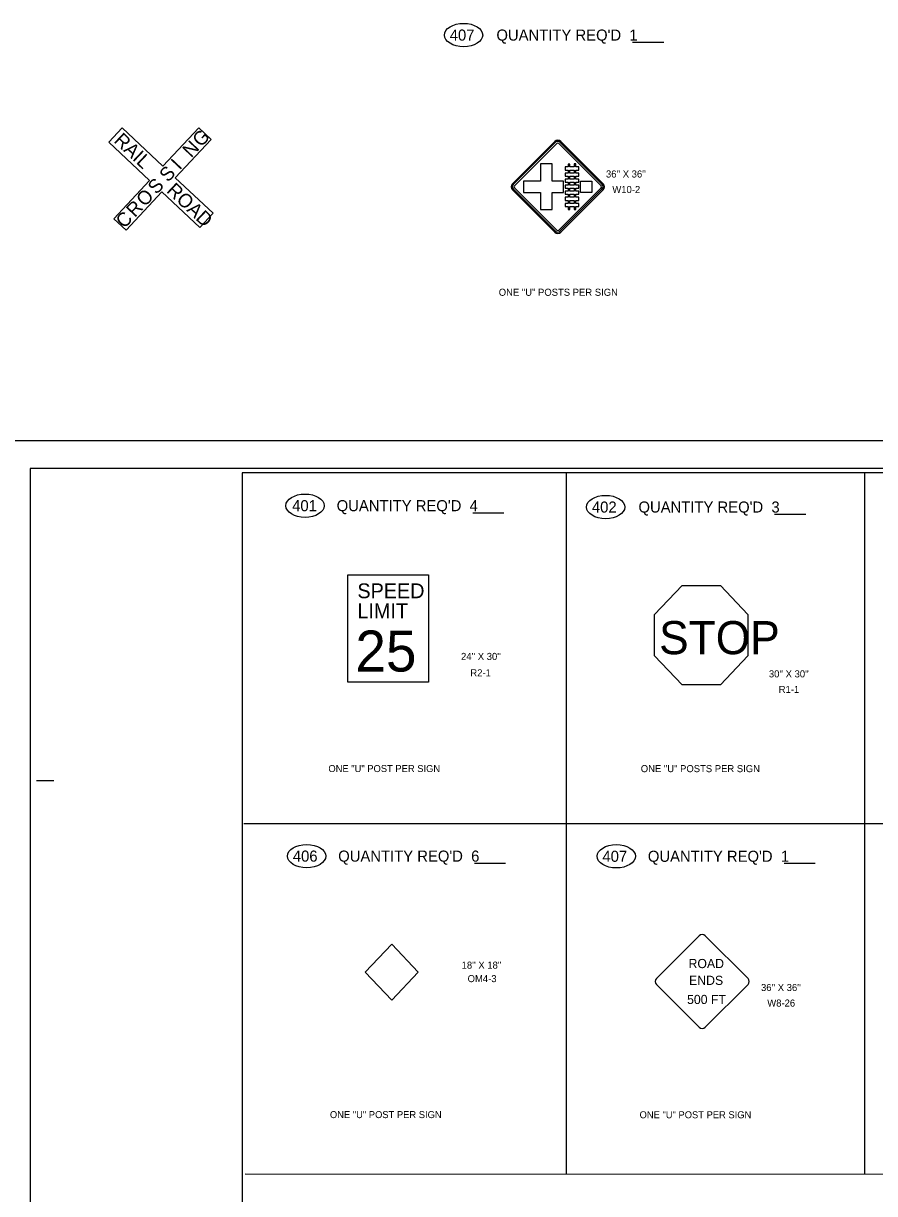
# Model space of a CAD drawing. Extents: x 2088420 to 2091362, y 751309 to 752707.
# Drawn here: x 2089077 to 2089693, y 751860 to 752707 of the extents above; entities that cross this region are included whole.
import ezdxf

# ---------------------------------------------------------------- set-up
doc = ezdxf.new("R2010")
doc.units = 0
for name, color, linetype in [('Default', 7, 'Continuous'), ('Prop Sign E', 7, 'Continuous'), ('Prop Text', 7, 'Continuous'), ('Sheet Block Title CELL', 7, 'Continuous'), ('Sheet Plot Border Inside CELL', 7, 'Continuous'), ('Sheet Plot Border Outside CELL', 7, 'Continuous')]:
    doc.layers.add(name, color=color, linetype=linetype)

msp = doc.modelspace()

# ---------------------------------------------------------------- linework, layer by layer
at = {"layer": 'Default'}
for p, q in [((2089469.52, 752381.51), (2089469.52, 752127.69)), ((2089685.4, 752381.62), (2089685.4, 752127.69)), ((2089236.2, 752127.69), (2090367.92, 752127.69)), ((2089469.52, 752127.69), (2089469.52, 751873.86)), ((2089685.4, 752127.8), (2089685.4, 751873.86)), ((2089237.3, 751873.98), (2090367.92, 751873.63))]:
    msp.add_line(p, q, dxfattribs=at)
for points in [[(2089311.54, 752229.8), (2089311.54, 752307.57), (2089369.91, 752307.57), (2089369.91, 752229.8)], [(2089533.57, 752278.84), (2089553.36, 752299.91), (2089581.32, 752299.91), (2089601.11, 752278.84), (2089601.11, 752249.04), (2089581.32, 752227.96), (2089553.36, 752227.96), (2089533.57, 752249.04)], [(2089343.25, 751999.57), (2089324.14, 752019.93), (2089343.25, 752040.29), (2089362.36, 752019.93)]]:
    msp.add_lwpolyline(points, close=True, dxfattribs=at)
at = {"layer": 'Prop Sign E'}
for p, q in [((2089138.42, 752620.78), (2089148.12, 752631.16)), ((2089148.12, 752631.16), (2089177.71, 752603.48)), ((2089177.71, 752603.48), (2089203.6, 752631.16)), ((2089203.6, 752631.16), (2089212.51, 752622.82)), ((2089168.01, 752593.11), (2089138.42, 752620.78)), ((2089212.51, 752622.82), (2089186.62, 752595.14)), ((2089461.25, 752621.37), (2089430.62, 752590.74)), ((2089461.86, 752620.76), (2089431.23, 752590.13)), ((2089432.08, 752589.28), (2089462.71, 752619.91)), ((2089464.17, 752619.91), (2089494.79, 752589.28)), ((2089495.64, 752590.13), (2089465.02, 752620.76)), ((2089496.25, 752590.74), (2089465.62, 752621.37)), ((2089142.12, 752565.43), (2089168.01, 752593.11)), ((2089186.62, 752595.14), (2089214.07, 752569.47)), ((2089176.92, 752584.77), (2089151.03, 752557.09)), ((2089204.36, 752559.1), (2089176.92, 752584.77)), ((2089430.62, 752586.36), (2089461.25, 752555.74)), ((2089431.23, 752586.97), (2089461.86, 752556.35)), ((2089462.71, 752557.2), (2089432.08, 752587.82)), ((2089494.79, 752587.82), (2089464.17, 752557.2)), ((2089465.02, 752556.35), (2089495.64, 752586.97)), ((2089465.62, 752555.74), (2089496.25, 752586.36)), ((2089214.07, 752569.47), (2089204.36, 752559.1)), ((2089151.03, 752557.09), (2089142.12, 752565.43)), ((2089565.76, 752046.38), (2089534.8, 752015.42)), ((2089601.13, 752015.42), (2089570.17, 752046.38)), ((2089534.8, 752011.01), (2089565.76, 751980.05)), ((2089570.17, 751980.05), (2089601.13, 752011.01))]:
    msp.add_line(p, q, dxfattribs=at)
for points in [[(2089467.56, 752584.43), (2089467.56, 752592.68), (2089459.31, 752592.68), (2089459.31, 752605.05), (2089451.06, 752605.05), (2089451.06, 752592.68), (2089438.69, 752592.68), (2089438.69, 752584.43), (2089451.06, 752584.43), (2089451.06, 752572.05), (2089459.31, 752572.05), (2089459.31, 752584.43)], [(2089478.6, 752600.68), (2089478.6, 752602.88), (2089476.41, 752602.88), (2089476.41, 752605.08), (2089475.37, 752605.08), (2089475.37, 752602.88), (2089472.13, 752602.88), (2089472.13, 752605.03), (2089471.06, 752605.03), (2089471.06, 752602.88), (2089468.87, 752602.88), (2089468.87, 752600.68), (2089471.06, 752600.68), (2089471.06, 752598.47), (2089468.87, 752598.47), (2089468.87, 752596.27), (2089471.06, 752596.27), (2089471.06, 752594.1), (2089468.87, 752594.1), (2089468.87, 752591.89), (2089471.06, 752591.89), (2089471.06, 752589.68), (2089468.87, 752589.68), (2089468.87, 752587.47), (2089471.06, 752587.47), (2089471.06, 752585.29), (2089468.87, 752585.29), (2089468.87, 752583.08), (2089471.06, 752583.08), (2089471.06, 752580.91), (2089468.87, 752580.91), (2089468.87, 752578.71), (2089471.06, 752578.71), (2089471.06, 752576.53), (2089468.87, 752576.53), (2089468.87, 752574.32), (2089471.06, 752574.32), (2089471.06, 752572.04), (2089472.13, 752572.04), (2089472.13, 752574.32), (2089475.37, 752574.32), (2089475.37, 752572.05), (2089476.41, 752572.05), (2089476.41, 752574.32), (2089478.6, 752574.32), (2089478.6, 752576.53), (2089476.41, 752576.53), (2089476.41, 752578.71), (2089478.6, 752578.71), (2089478.6, 752580.91), (2089476.41, 752580.91), (2089476.41, 752583.08), (2089478.6, 752583.08), (2089478.6, 752585.29), (2089476.41, 752585.29), (2089476.41, 752587.47), (2089478.6, 752587.47), (2089478.6, 752589.68), (2089476.41, 752589.68), (2089476.41, 752591.89), (2089478.6, 752591.89), (2089478.6, 752594.1), (2089476.41, 752594.1), (2089476.41, 752596.27), (2089478.6, 752596.27), (2089478.6, 752598.47), (2089476.41, 752598.47), (2089476.41, 752600.68)], [(2089472.13, 752600.68), (2089475.37, 752600.68), (2089475.37, 752598.47), (2089472.13, 752598.47)], [(2089472.13, 752596.27), (2089475.37, 752596.27), (2089475.37, 752594.1), (2089472.13, 752594.1)], [(2089479.94, 752592.68), (2089488.19, 752592.68), (2089488.19, 752584.43), (2089479.94, 752584.43)], [(2089472.13, 752591.89), (2089475.37, 752591.89), (2089475.37, 752589.68), (2089472.13, 752589.68)], [(2089472.13, 752587.47), (2089475.37, 752587.47), (2089475.37, 752585.29), (2089472.13, 752585.29)], [(2089472.13, 752583.08), (2089475.37, 752583.08), (2089475.37, 752580.91), (2089472.13, 752580.91)], [(2089472.13, 752578.71), (2089475.37, 752578.71), (2089475.37, 752576.53), (2089472.13, 752576.53)]]:
    msp.add_lwpolyline(points, close=True, dxfattribs=at)
for centre, radius, start, end in [((2089463.44, 752619.18), 3.09, 45, 135), ((2089463.44, 752619.18), 2.23, 45, 135), ((2089463.44, 752619.18), 1.03, 45, 135), ((2089432.81, 752588.55), 3.09, 135, 225), ((2089432.81, 752588.55), 2.23, 135, 225), ((2089432.81, 752588.55), 1.03, 135, 225), ((2089494.06, 752588.55), 1.03, 315, 45), ((2089494.06, 752588.55), 2.23, 315, 45), ((2089494.06, 752588.55), 3.09, 315, 45), ((2089463.44, 752557.93), 3.09, 225, 315), ((2089463.44, 752557.93), 2.23, 225, 315), ((2089463.44, 752557.93), 1.03, 225, 315), ((2089567.96, 752044.17), 3.12, 45, 135), ((2089537.01, 752013.21), 3.12, 135, 225), ((2089598.92, 752013.21), 3.12, 315, 45), ((2089567.96, 751982.26), 3.12, 225, 315)]:
    msp.add_arc(centre, radius, start, end, dxfattribs=at)
at = {"layer": 'Prop Text'}
for p, q in [((2089540.11, 752693.03), (2089517.58, 752693.03)), ((2089424.5, 752352.33), (2089401.97, 752352.33)), ((2089642.91, 752351.34), (2089620.38, 752351.34)), ((2089425.6, 752098.62), (2089403.07, 752098.62)), ((2089649.7, 752098.51), (2089627.18, 752098.51))]:
    msp.add_line(p, q, dxfattribs=at)
for centre in [(2089395.26, 752698.38), (2089280.58, 752357.68), (2089498.06, 752356.69), (2089281.69, 752103.97), (2089505.79, 752103.86)]:
    msp.add_ellipse(centre, major_axis=(-13.87, 0), ratio=0.608767, dxfattribs=at)
at = {"layer": 'Sheet Block Title CELL'}
msp.add_lwpolyline([(2090735.1, 752381.4), (2089235.1, 752381.4), (2089235.1, 751331.4), (2090735.1, 751331.4)], close=True, dxfattribs=at)
at = {"layer": 'Sheet Plot Border Inside CELL'}
msp.add_line((2089086.15, 752158.82), (2089098.65, 752158.82), dxfattribs=at)
msp.add_lwpolyline([(2090747.03, 752384.71), (2089081.6, 752384.71), (2089081.6, 751328.81), (2090747.03, 751328.81)], close=True, dxfattribs=at)
at = {"layer": 'Sheet Plot Border Outside CELL'}
msp.add_lwpolyline([(2090751.52, 752404.71), (2089068.61, 752404.71), (2089068.61, 751308.81), (2090751.52, 751308.81)], close=True, dxfattribs=at)

# ---------------------------------------------------------------- texts
at = {"layer": 'Default'}
for s, height, p in [("36'' X 36''", 5.1183, (2089498.34, 752595.25)), ('W10-2', 5.118, (2089502.94, 752584.01)), ('ONE "U" POSTS PER SIGN', 5.1184, (2089420.73, 752509.62)), ('SPEED', 10.71, (2089318.44, 752290.69)), ('LIMIT', 10.71, (2089318.44, 752276.16)), ('STOP', 23.981, (2089536.79, 752250.15)), ('25', 29.712, (2089316.99, 752237.59)), ("24'' X 30''", 5.1184, (2089393.44, 752245.98)), ('R2-1', 5.118, (2089400.19, 752234.09)), ("30'' X 30''", 5.1183, (2089616.24, 752233.35)), ('R1-1', 5.118, (2089623.35, 752222.11)), ('ONE "U" POSTS PER SIGN', 5.1184, (2089523.53, 752164.75)), ("18'' X 18''", 5.1184, (2089393.86, 752022.49)), ('OM4-3', 5.118, (2089398.2, 752012.73)), ("36'' X 36''", 5.1183, (2089610.53, 752006.28)), ('W8-26', 5.118, (2089615.07, 751995.04))]:
    msp.add_text(s, height=height, dxfattribs=at).set_placement(p)
at = {"layer": 'Prop Sign E'}
for s, rotation, p in [('RAIL', 316.69502, (2089141.61, 752621.23)), ('G', 46.69326, (2089205.28, 752616.75)), ('N', 46.69326, (2089198.11, 752609.15)), ('S', 46.69326, (2089181.36, 752591.37)), ('I', 46.69326, (2089189.74, 752600.26)), ('S', 46.69326, (2089172.98, 752582.49)), ('O', 46.69326, (2089164.61, 752573.6)), ('ROAD', 316.69502, (2089179.72, 752585.08)), ('R', 46.69326, (2089157.37, 752565.92)), ('C', 46.69326, (2089149.81, 752557.9))]:
    msp.add_text(s, height=10, rotation=rotation, dxfattribs=at).set_placement(p)
for s, p in [('ROAD', (2089558.1, 752022.89)), ('ENDS', (2089558.48, 752010.73)), ('500 FT', (2089557.02, 751996.89))]:
    msp.add_text(s, height=6.64, dxfattribs=at).set_placement(p)
at = {"layer": 'Prop Text'}
for s, height, p in [('407', 8.023, (2089385.25, 752694.36)), ("QUANTITY REQ'D  1", 8.0231, (2089419.04, 752694.36)), ('401', 8.023, (2089271.22, 752353.67)), ("QUANTITY REQ'D  4", 8.0231, (2089303.43, 752353.67)), ('402', 8.023, (2089488.16, 752352.68)), ("QUANTITY REQ'D  3", 8.0231, (2089521.84, 752352.68)), ('ONE "U" POST PER SIGN', 5.0672, (2089297.44, 752164.82)), ('406', 8.023, (2089271.7, 752099.96)), ("QUANTITY REQ'D  6", 8.0231, (2089304.53, 752099.96)), ('407', 8.023, (2089495.78, 752099.85)), ("QUANTITY REQ'D  1", 8.0231, (2089528.64, 752099.85)), ('ONE "U" POST PER SIGN', 5.0672, (2089298.54, 751914.3)), ('ONE "U" POST PER SIGN', 5.0672, (2089522.65, 751914.19))]:
    msp.add_text(s, height=height, dxfattribs=at).set_placement(p)

doc.saveas('drawing.dxf')
